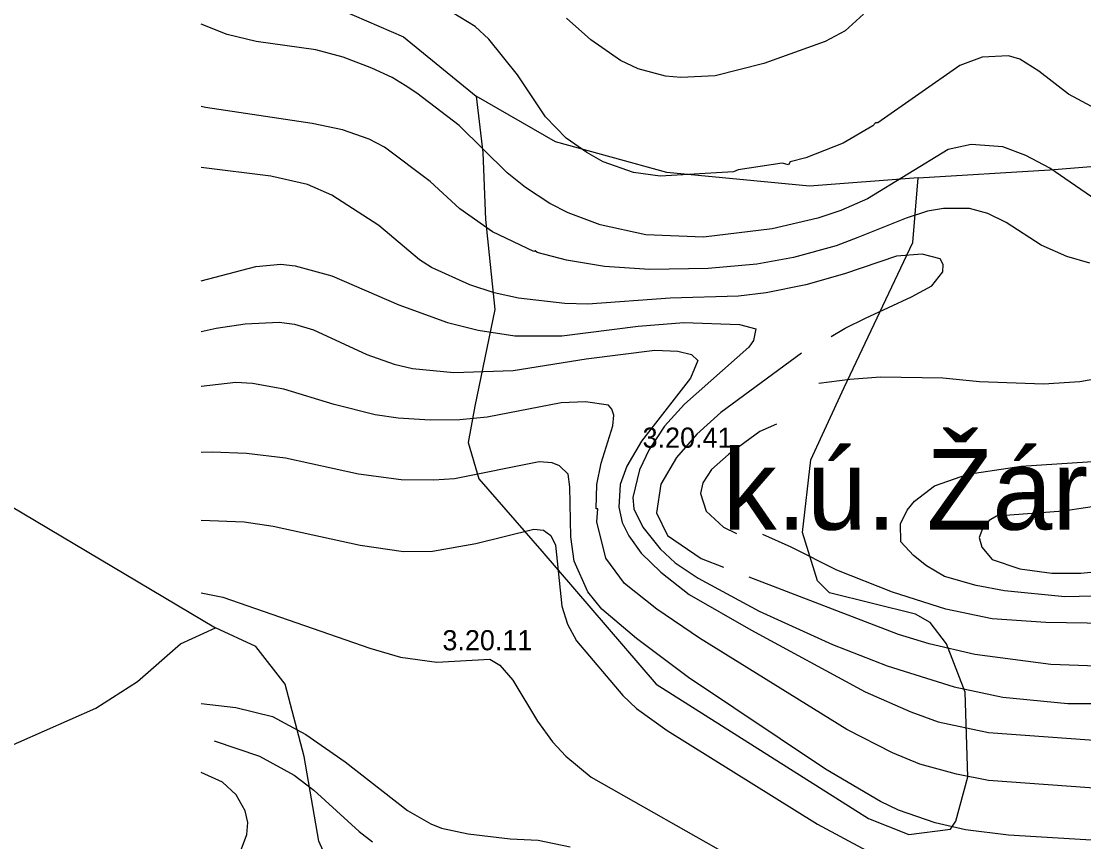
# Model space of a CAD drawing. Extents: x -662500 to -655523, y -1056000 to -1049993.
# Drawn here: x -661659.2 to -661263.9, y -1051925.7 to -1051620.1 of the extents above; entities that cross this region are included whole.
import ezdxf

# ---------------------------------------------------------------- set-up
doc = ezdxf.new("R2010")
doc.units = 0
for name, color, linetype in [('58', 7, 'Continuous'), ('Vrstva 24', 7, 'Continuous'), ('Vrstva 7', 7, 'Continuous')]:
    doc.layers.add(name, color=color, linetype=linetype)

msp = doc.modelspace()

# ---------------------------------------------------------------- linework, layer by layer
at = {"layer": 'Vrstva 24'}
for points in [[(-661544.5, -1051614), (-661517, -1051626), (-661490, -1051648)], [(-661490, -1051648), (-661487.5, -1051669), (-661486.5, -1051694), (-661483, -1051727.5), (-661490.5, -1051763.5), (-661493, -1051777), (-661489, -1051790.5), (-661465.5, -1051817.5), (-661423, -1051867), (-661344, -1051917), (-661329, -1051923), (-661313.5, -1051921), (-661311.5, -1051918), (-661307, -1051901.5), (-661308, -1051870), (-661315, -1051852), (-661321, -1051844), (-661326.5, -1051841), (-661358.5, -1051833), (-661363, -1051828.5), (-661368.5, -1051810.5), (-661365.5, -1051783.5), (-661353, -1051756.5), (-661327.5, -1051702.5), (-661325.5, -1051678.5)], [(-661325.5, -1051678.5), (-661366, -1051681.5), (-661419, -1051676.5), (-661460.5, -1051665), (-661490, -1051648)], [(-661325.5, -1051678.5), (-661276.5, -1051675.5), (-661191, -1051668.5), (-661149.5, -1051670), (-661133, -1051674), (-661124.5, -1051677.5), (-661112, -1051684), (-661104.5, -1051691.5), (-661026, -1051781.5), (-661005, -1051798), (-660983, -1051806.5), (-660947.48, -1051815.82)], [(-661882, -1051673), (-661865.5, -1051680), (-661808.5, -1051691), (-661771.5, -1051702.5), (-661762, -1051705), (-661744, -1051714.5), (-661731, -1051722), (-661713.5, -1051737.5), (-661704, -1051747), (-661687, -1051769), (-661663.5, -1051800.5), (-661587, -1051846)], [(-661750, -1052071.5), (-661753.5, -1052056), (-661750, -1052022), (-661748.36, -1052000), (-661747.5, -1051988.5), (-661737.5, -1051952.5), (-661720, -1051923.5), (-661698.5, -1051905.5), (-661631.5, -1051876), (-661616, -1051866), (-661600, -1051852), (-661587, -1051846)], [(-661191, -1052048), (-661295, -1052071.5), (-661327.5, -1052073.5), (-661352, -1052066.5), (-661463.18, -1052000), (-661512.5, -1051970.5), (-661540.5, -1051943.5), (-661548.5, -1051925.5), (-661554, -1051894), (-661561, -1051867), (-661572, -1051853), (-661587, -1051846)]]:
    msp.add_lwpolyline(points, dxfattribs=at)
at = {"layer": 'Vrstva 7'}
for p, q in [((-661490.38, -1051622.14), (-661501.71, -1051615.19)), ((-661345.83, -1051617.46), (-661352.63, -1051623.7)), ((-661582.62, -1051625.1), (-661592.25, -1051621.27)), ((-661447.29, -1051627.1), (-661456.36, -1051619.02)), ((-661571.86, -1051627.66), (-661582.62, -1051625.1)), ((-661485.27, -1051626.81), (-661490.38, -1051622.14)), ((-661352.63, -1051623.7), (-661360.14, -1051627.66)), ((-661549.61, -1051630.78), (-661571.86, -1051627.66)), ((-661474.65, -1051640.14), (-661485.27, -1051626.81)), ((-661436.24, -1051634.75), (-661447.29, -1051627.1)), ((-661360.14, -1051627.66), (-661382.95, -1051635.88)), ((-661539.41, -1051633.47), (-661549.61, -1051630.78)), ((-661291.97, -1051633.05), (-661301.75, -1051633.47)), ((-661287.72, -1051634.32), (-661291.97, -1051633.05)), ((-661528.78, -1051637.58), (-661539.41, -1051633.47)), ((-661429.72, -1051637.87), (-661436.24, -1051634.75)), ((-661382.95, -1051635.88), (-661401.09, -1051640.42)), ((-661309.97, -1051636.59), (-661340.58, -1051657.99)), ((-661301.75, -1051633.47), (-661309.97, -1051636.59)), ((-661280.64, -1051638.72), (-661287.72, -1051634.32)), ((-661521.23, -1051641.12), (-661528.78, -1051637.58)), ((-661516.43, -1051644.1), (-661521.23, -1051641.12)), ((-661464.16, -1051655.72), (-661474.65, -1051640.14)), ((-661419.52, -1051640.56), (-661429.72, -1051637.87)), ((-661413.85, -1051641.13), (-661419.52, -1051640.56)), ((-661401.09, -1051640.42), (-661413.85, -1051641.13)), ((-661269.58, -1051647.36), (-661280.64, -1051638.72)), ((-661512.06, -1051646.88), (-661516.43, -1051644.1)), ((-661496.3, -1051659.01), (-661512.06, -1051646.88)), ((-661261.08, -1051651.9), (-661269.58, -1051647.36)), ((-661590.71, -1051652.32), (-661592.25, -1051651.94)), ((-661551.03, -1051658.27), (-661590.71, -1051652.32)), ((-661456.51, -1051663.66), (-661464.16, -1051655.72)), ((-661539.69, -1051660.54), (-661551.03, -1051658.27)), ((-661529.77, -1051664.08), (-661539.69, -1051660.54)), ((-661478.47, -1051676.56), (-661496.3, -1051659.01)), ((-661342.42, -1051659.12), (-661353.48, -1051665.5)), ((-661341.43, -1051657.99), (-661342.42, -1051659.12)), ((-661340.58, -1051657.99), (-661341.43, -1051657.99)), ((-661524.1, -1051667.06), (-661529.77, -1051664.08)), ((-661448.85, -1051669.04), (-661456.51, -1051663.66)), ((-661507.1, -1051679.81), (-661524.1, -1051667.06)), ((-661442.76, -1051672.45), (-661448.85, -1051669.04)), ((-661353.48, -1051665.5), (-661367.37, -1051671.03)), ((-661314.36, -1051667.91), (-661344.41, -1051686.33)), ((-661305.86, -1051666.07), (-661314.36, -1051667.91)), ((-661293.96, -1051666.92), (-661305.86, -1051666.07)), ((-661285.45, -1051670.18), (-661293.96, -1051666.92)), ((-661431.42, -1051676.41), (-661442.76, -1051672.45)), ((-661373.18, -1051672.45), (-661373.74, -1051673.58)), ((-661367.37, -1051671.03), (-661373.18, -1051672.45)), ((-661276.53, -1051674.85), (-661285.45, -1051670.18)), ((-661566.34, -1051677.83), (-661592.25, -1051674.67)), ((-661471.67, -1051682.08), (-661478.47, -1051676.56)), ((-661421.5, -1051677.83), (-661431.42, -1051676.41)), ((-661394.29, -1051676.27), (-661421.5, -1051677.83)), ((-661392.45, -1051675.42), (-661394.29, -1051676.27)), ((-661376.15, -1051673.01), (-661392.45, -1051675.42)), ((-661373.74, -1051673.58), (-661376.15, -1051673.01)), ((-661257.4, -1051688.03), (-661276.53, -1051674.85)), ((-661552.73, -1051680.95), (-661566.34, -1051677.83)), ((-661496.05, -1051690.02), (-661507.1, -1051679.81)), ((-661543.66, -1051684.92), (-661552.73, -1051680.95)), ((-661462.6, -1051688.03), (-661471.67, -1051682.08)), ((-661526.23, -1051696.25), (-661543.66, -1051684.92)), ((-661455.8, -1051691.44), (-661462.6, -1051688.03)), ((-661344.41, -1051686.33), (-661354.33, -1051690.59)), ((-661483.86, -1051698.52), (-661496.05, -1051690.02)), ((-661443.89, -1051695.97), (-661455.8, -1051691.44)), ((-661354.33, -1051690.59), (-661362.83, -1051693.42)), ((-661322.02, -1051690.87), (-661329.95, -1051693.42)), ((-661316.07, -1051689.88), (-661322.02, -1051690.87)), ((-661306.43, -1051689.88), (-661316.07, -1051689.88)), ((-661299.63, -1051691.72), (-661306.43, -1051689.88)), ((-661292.82, -1051695.12), (-661299.63, -1051691.72)), ((-661511.07, -1051709.01), (-661526.23, -1051696.25)), ((-661426.89, -1051699.66), (-661443.89, -1051695.97)), ((-661362.83, -1051693.42), (-661379.84, -1051697.39)), ((-661329.95, -1051693.42), (-661346.11, -1051699.94)), ((-661279.79, -1051703.48), (-661292.82, -1051695.12)), ((-661468.55, -1051705.89), (-661483.86, -1051698.52)), ((-661405.35, -1051700.51), (-661426.89, -1051699.66)), ((-661379.84, -1051697.39), (-661405.35, -1051700.51)), ((-661347.95, -1051700.65), (-661356.03, -1051703.77)), ((-661346.11, -1051699.94), (-661347.95, -1051700.65)), ((-661356.03, -1051703.77), (-661371.9, -1051708.16)), ((-661270.15, -1051707.73), (-661279.79, -1051703.48)), ((-661467.98, -1051705.61), (-661468.55, -1051705.89)), ((-661467.28, -1051706.32), (-661467.98, -1051705.61)), ((-661456.36, -1051709.15), (-661467.28, -1051706.32)), ((-661371.9, -1051708.16), (-661385.51, -1051710.57)), ((-661333.64, -1051707.59), (-661352.91, -1051714.25)), ((-661324, -1051706.88), (-661333.64, -1051707.59)), ((-661317.34, -1051708.58), (-661324, -1051706.88)), ((-661261.65, -1051710.28), (-661270.15, -1051707.73)), ((-661592.25, -1051716.86), (-661572.01, -1051711.42)), ((-661592.25, -1051716.86), (-661572.01, -1051711.42)), ((-661572.01, -1051711.42), (-661562.65, -1051710.57)), ((-661572.01, -1051711.42), (-661562.65, -1051710.57)), ((-661562.65, -1051710.57), (-661557.27, -1051711.28)), ((-661562.65, -1051710.57), (-661557.27, -1051711.28)), ((-661557.27, -1051711.28), (-661543.66, -1051714.96)), ((-661557.27, -1051711.28), (-661543.66, -1051714.96)), ((-661506.53, -1051711.84), (-661511.07, -1051709.01)), ((-661492.36, -1051718.36), (-661506.53, -1051711.84)), ((-661442.19, -1051711.42), (-661456.36, -1051709.15)), ((-661425.47, -1051712.55), (-661442.19, -1051711.42)), ((-661403.65, -1051712.27), (-661425.47, -1051712.55)), ((-661385.51, -1051710.57), (-661403.65, -1051712.27)), ((-661316.21, -1051710.71), (-661317.34, -1051708.58)), ((-661316.35, -1051713.4), (-661316.21, -1051710.71)), ((-661543.66, -1051714.96), (-661518.72, -1051725.73)), ((-661543.66, -1051714.96), (-661518.72, -1051725.73)), ((-661352.91, -1051714.25), (-661367.37, -1051718.36)), ((-661320.46, -1051718.65), (-661316.35, -1051713.4)), ((-661483.29, -1051721.34), (-661492.36, -1051718.36)), ((-661367.37, -1051718.36), (-661382.1, -1051721.34)), ((-661327.97, -1051722.76), (-661320.46, -1051718.65)), ((-661474.22, -1051723.32), (-661483.29, -1051721.34)), ((-661456.93, -1051725.31), (-661474.22, -1051723.32)), ((-661417.82, -1051723.32), (-661448.43, -1051725.45)), ((-661392.31, -1051722.47), (-661417.82, -1051723.32)), ((-661382.1, -1051721.34), (-661392.31, -1051722.47)), ((-661345.09, -1051730.72), (-661327.97, -1051722.76)), ((-661518.72, -1051725.73), (-661500.58, -1051732.39)), ((-661518.72, -1051725.73), (-661500.58, -1051732.39)), ((-661448.43, -1051725.45), (-661456.93, -1051725.31)), ((-661575.97, -1051732.82), (-661563.22, -1051732.25)), ((-661575.97, -1051732.82), (-661563.22, -1051732.25)), ((-661563.22, -1051732.25), (-661557.55, -1051732.96)), ((-661563.22, -1051732.25), (-661557.55, -1051732.96)), ((-661352.65, -1051734.48), (-661345.09, -1051730.72)), ((-661592.25, -1051735.65), (-661586.74, -1051734.38)), ((-661592.25, -1051735.65), (-661586.74, -1051734.38)), ((-661586.74, -1051734.38), (-661575.97, -1051732.82)), ((-661586.74, -1051734.38), (-661575.97, -1051732.82)), ((-661557.55, -1051732.96), (-661550.46, -1051735.08)), ((-661557.55, -1051732.96), (-661550.46, -1051735.08)), ((-661550.46, -1051735.08), (-661530.62, -1051744.3)), ((-661550.46, -1051735.08), (-661530.62, -1051744.3)), ((-661500.58, -1051732.39), (-661489.24, -1051735.23)), ((-661500.58, -1051732.39), (-661489.24, -1051735.23)), ((-661489.24, -1051735.23), (-661475.64, -1051737.35)), ((-661489.24, -1051735.23), (-661475.64, -1051737.35)), ((-661458.07, -1051737.35), (-661429.72, -1051733.67)), ((-661458.07, -1051737.35), (-661429.72, -1051733.67)), ((-661429.72, -1051733.67), (-661412.72, -1051732.39)), ((-661429.72, -1051733.67), (-661412.72, -1051732.39)), ((-661412.72, -1051732.39), (-661392.03, -1051733.1)), ((-661412.72, -1051732.39), (-661392.03, -1051733.1)), ((-661392.03, -1051733.1), (-661385.93, -1051734.66)), ((-661392.03, -1051733.1), (-661385.93, -1051734.66)), ((-661385.93, -1051734.66), (-661386.78, -1051739.05)), ((-661385.93, -1051734.66), (-661386.78, -1051739.05)), ((-661357.93, -1051737.48), (-661352.65, -1051734.48)), ((-661475.64, -1051737.35), (-661458.07, -1051737.35)), ((-661475.64, -1051737.35), (-661458.07, -1051737.35)), ((-661386.78, -1051739.05), (-661388.48, -1051741.46)), ((-661386.78, -1051739.05), (-661388.48, -1051741.46)), ((-661448.99, -1051745.85), (-661423.49, -1051742.6)), ((-661448.99, -1051745.85), (-661423.49, -1051742.6)), ((-661423.49, -1051742.6), (-661414.98, -1051743.02)), ((-661423.49, -1051742.6), (-661414.98, -1051743.02)), ((-661414.98, -1051743.02), (-661409.88, -1051744.3)), ((-661414.98, -1051743.02), (-661409.88, -1051744.3)), ((-661388.48, -1051741.46), (-661412.43, -1051762.72)), ((-661388.48, -1051741.46), (-661412.43, -1051762.72)), ((-661368.97, -1051743.8), (-661398.97, -1051765.84)), ((-661530.62, -1051744.3), (-661520.42, -1051747.84)), ((-661530.62, -1051744.3), (-661520.42, -1051747.84)), ((-661520.42, -1051747.84), (-661513.62, -1051749.4)), ((-661520.42, -1051747.84), (-661513.62, -1051749.4)), ((-661476.2, -1051750.25), (-661448.99, -1051745.85)), ((-661476.2, -1051750.25), (-661448.99, -1051745.85)), ((-661407.47, -1051746.42), (-661410.17, -1051753.08)), ((-661407.47, -1051746.42), (-661410.17, -1051753.08)), ((-661409.88, -1051744.3), (-661407.47, -1051746.42)), ((-661409.88, -1051744.3), (-661407.47, -1051746.42)), ((-661513.62, -1051749.4), (-661498.31, -1051750.96)), ((-661513.62, -1051749.4), (-661498.31, -1051750.96)), ((-661498.31, -1051750.96), (-661476.2, -1051750.25)), ((-661498.31, -1051750.96), (-661476.2, -1051750.25)), ((-661265.33, -1051754.36), (-661251.73, -1051751.81)), ((-661579.37, -1051754.64), (-661592.25, -1051756.19)), ((-661573.14, -1051755.07), (-661579.37, -1051754.64)), ((-661561.52, -1051757.19), (-661573.14, -1051755.07)), ((-661410.17, -1051753.08), (-661428.45, -1051776.47)), ((-661410.17, -1051753.08), (-661428.45, -1051776.47)), ((-661362.52, -1051754.92), (-661350.93, -1051753.37)), ((-661350.93, -1051753.37), (-661339.59, -1051752.52)), ((-661339.59, -1051752.52), (-661316.35, -1051752.94)), ((-661316.35, -1051752.94), (-661302.74, -1051754.36)), ((-661302.74, -1051754.36), (-661278.94, -1051755.21)), ((-661278.94, -1051755.21), (-661265.33, -1051754.36)), ((-661542.81, -1051762.86), (-661561.52, -1051757.19)), ((-661527.51, -1051766.69), (-661542.81, -1051762.86)), ((-661458.35, -1051762.29), (-661485.84, -1051767.54)), ((-661449.28, -1051761.87), (-661458.35, -1051762.29)), ((-661440.78, -1051763.15), (-661449.28, -1051761.87)), ((-661439.5, -1051764.56), (-661440.78, -1051763.15)), ((-661412.43, -1051762.72), (-661419.94, -1051770.94)), ((-661412.43, -1051762.72), (-661419.94, -1051770.94)), ((-661519, -1051767.96), (-661527.51, -1051766.69)), ((-661485.84, -1051767.54), (-661496.05, -1051768.53)), ((-661438.79, -1051766.83), (-661439.5, -1051764.56)), ((-661439.08, -1051770.8), (-661438.79, -1051766.83)), ((-661398.97, -1051765.84), (-661407.9, -1051773.92)), ((-661507.1, -1051768.67), (-661519, -1051767.96)), ((-661496.05, -1051768.53), (-661507.1, -1051768.67)), ((-661443.47, -1051784.69), (-661439.08, -1051770.8)), ((-661419.94, -1051770.94), (-661425.61, -1051779.58)), ((-661419.94, -1051770.94), (-661425.61, -1051779.58)), ((-661378.28, -1051770.23), (-661384.37, -1051772.92)), ((-661407.9, -1051773.92), (-661415.41, -1051782.56)), ((-661384.37, -1051772.92), (-661396.14, -1051781.43)), ((-661428.45, -1051776.47), (-661433.97, -1051785.82)), ((-661428.45, -1051776.47), (-661433.97, -1051785.82)), ((-661425.61, -1051779.58), (-661429.16, -1051787.24)), ((-661425.61, -1051779.58), (-661429.16, -1051787.24)), ((-661588.16, -1051780.58), (-661592.25, -1051780.7)), ((-661575.41, -1051781.14), (-661588.16, -1051780.58)), ((-661560.95, -1051782.84), (-661575.41, -1051781.14)), ((-661533.74, -1051788.79), (-661560.95, -1051782.84)), ((-661415.41, -1051782.56), (-661421.22, -1051792.48)), ((-661396.14, -1051781.43), (-661402.37, -1051787.09)), ((-661287.16, -1051785.82), (-661243.79, -1051782.99)), ((-661466.57, -1051784.26), (-661498.03, -1051790.5)), ((-661461.75, -1051784.54), (-661466.57, -1051784.26)), ((-661458.92, -1051785.68), (-661461.75, -1051784.54)), ((-661455.8, -1051788.8), (-661458.92, -1051785.68)), ((-661445.03, -1051792.62), (-661443.47, -1051784.69)), ((-661433.97, -1051785.82), (-661436.38, -1051792.62)), ((-661433.97, -1051785.82), (-661436.38, -1051792.62)), ((-661429.16, -1051787.24), (-661431.71, -1051797.44)), ((-661429.16, -1051787.24), (-661431.71, -1051797.44)), ((-661402.37, -1051787.09), (-661405.63, -1051792.05)), ((-661306.99, -1051788.79), (-661287.16, -1051785.82)), ((-661517.87, -1051790.92), (-661533.74, -1051788.79)), ((-661505.68, -1051791.06), (-661517.87, -1051790.92)), ((-661498.03, -1051790.5), (-661505.68, -1051791.06)), ((-661455.09, -1051793.47), (-661455.8, -1051788.8)), ((-661319.47, -1051793.19), (-661306.99, -1051788.79)), ((-661454.81, -1051812.18), (-661455.09, -1051793.47)), ((-661445.31, -1051801.69), (-661445.03, -1051792.62)), ((-661436.38, -1051792.62), (-661436.95, -1051801.12)), ((-661436.38, -1051792.62), (-661436.95, -1051801.12)), ((-661421.22, -1051792.48), (-661422.92, -1051803.25)), ((-661405.63, -1051792.05), (-661406.48, -1051796.02)), ((-661326.83, -1051798.86), (-661319.47, -1051793.19)), ((-661431.71, -1051797.44), (-661431.28, -1051801.69)), ((-661431.71, -1051797.44), (-661431.28, -1051801.69)), ((-661406.48, -1051796.02), (-661404.35, -1051802.54)), ((-661329.67, -1051802.26), (-661326.83, -1051798.86)), ((-661244.07, -1051798.43), (-661271.57, -1051802.54)), ((-661444.74, -1051801.69), (-661445.31, -1051801.69)), ((-661445.03, -1051806.51), (-661444.74, -1051801.69)), ((-661436.95, -1051801.12), (-661435.67, -1051806.79)), ((-661436.95, -1051801.12), (-661435.67, -1051806.79)), ((-661431.28, -1051801.69), (-661428.02, -1051808.49)), ((-661431.28, -1051801.69), (-661428.02, -1051808.49)), ((-661422.92, -1051803.25), (-661418.81, -1051811.61)), ((-661404.35, -1051802.54), (-661397.91, -1051808.56)), ((-661332.08, -1051807.36), (-661329.67, -1051802.26)), ((-661271.57, -1051802.54), (-661296.4, -1051804.42)), ((-661592.25, -1051805.95), (-661576.26, -1051806.51)), ((-661576.26, -1051806.51), (-661565.49, -1051808.21)), ((-661441.77, -1051820.11), (-661445.03, -1051806.51)), ((-661435.67, -1051806.79), (-661433.12, -1051811.75)), ((-661435.67, -1051806.79), (-661433.12, -1051811.75)), ((-661331.94, -1051814.02), (-661332.08, -1051807.36)), ((-661299.14, -1051806.02), (-661301.41, -1051808.75)), ((-661296.4, -1051804.42), (-661299.14, -1051806.02)), ((-661565.49, -1051808.21), (-661533.18, -1051815.3)), ((-661490.09, -1051814.59), (-661468.55, -1051809.34)), ((-661468.55, -1051809.34), (-661464.87, -1051809.72)), ((-661464.87, -1051809.72), (-661462.18, -1051811.61)), ((-661428.02, -1051808.49), (-661421.5, -1051816.57)), ((-661428.02, -1051808.49), (-661421.5, -1051816.57)), ((-661397.91, -1051808.56), (-661393.16, -1051810.9)), ((-661372.75, -1051816.01), (-661383.33, -1051811.28)), ((-661301.41, -1051808.75), (-661302.78, -1051812.4)), ((-661533.18, -1051815.3), (-661517.02, -1051817.56)), ((-661506.25, -1051817.42), (-661490.09, -1051814.59)), ((-661462.18, -1051811.61), (-661460.47, -1051815.3)), ((-661460.47, -1051815.3), (-661458.07, -1051837.97)), ((-661453.53, -1051821.25), (-661454.81, -1051812.18)), ((-661433.12, -1051811.75), (-661428.59, -1051818.27)), ((-661433.12, -1051811.75), (-661428.59, -1051818.27)), ((-661418.81, -1051811.61), (-661406.2, -1051820.26)), ((-661327.26, -1051819.12), (-661331.94, -1051814.02)), ((-661302.78, -1051812.4), (-661301.87, -1051815.94)), ((-661517.02, -1051817.56), (-661506.25, -1051817.42)), ((-661428.59, -1051818.27), (-661421.22, -1051825.36)), ((-661428.59, -1051818.27), (-661421.22, -1051825.36)), ((-661421.5, -1051816.57), (-661415.97, -1051821.81)), ((-661421.5, -1051816.57), (-661415.97, -1051821.81)), ((-661355.75, -1051824.51), (-661372.75, -1051816.01)), ((-661322.44, -1051822.95), (-661327.26, -1051819.12)), ((-661301.87, -1051815.94), (-661297.93, -1051820.54)), ((-661448.43, -1051832.59), (-661453.53, -1051821.25)), ((-661434.82, -1051829.47), (-661441.77, -1051820.11)), ((-661415.97, -1051821.81), (-661407.33, -1051827.48)), ((-661415.97, -1051821.81), (-661407.33, -1051827.48)), ((-661406.2, -1051820.26), (-661397.96, -1051823.42)), ((-661315.78, -1051826.92), (-661322.44, -1051822.95)), ((-661297.93, -1051820.54), (-661287.72, -1051824.08)), ((-661421.22, -1051825.36), (-661410.73, -1051833.58)), ((-661421.22, -1051825.36), (-661410.73, -1051833.58)), ((-661332.79, -1051848.46), (-661388.36, -1051827.11)), ((-661335.06, -1051832.73), (-661355.75, -1051824.51)), ((-661303.88, -1051830.32), (-661315.78, -1051826.92)), ((-661287.72, -1051824.08), (-661275.82, -1051825.64)), ((-661275.82, -1051825.64), (-661265.05, -1051825.64)), ((-661265.05, -1051825.64), (-661248.13, -1051824.07)), ((-661422.78, -1051839.1), (-661434.82, -1051829.47)), ((-661407.33, -1051827.48), (-661384.66, -1051839.81)), ((-661407.33, -1051827.48), (-661384.66, -1051839.81)), ((-661293.39, -1051832.3), (-661303.88, -1051830.32)), ((-661592.25, -1051832.94), (-661584.19, -1051834.57)), ((-661584.19, -1051834.57), (-661529.49, -1051853.56)), ((-661443.19, -1051839.1), (-661448.43, -1051832.59)), ((-661410.73, -1051833.58), (-661387.77, -1051846.76)), ((-661410.73, -1051833.58), (-661387.77, -1051846.76)), ((-661315.21, -1051839.1), (-661335.06, -1051832.73)), ((-661271, -1051834.43), (-661293.39, -1051832.3)), ((-661248.61, -1051834), (-661271, -1051834.43)), ((-661458.07, -1051837.97), (-661455.94, -1051844.63)), ((-661430.29, -1051850.02), (-661443.19, -1051839.1)), ((-661406.91, -1051849.88), (-661422.78, -1051839.1)), ((-661384.66, -1051839.81), (-661357.45, -1051852.28)), ((-661384.66, -1051839.81), (-661357.45, -1051852.28)), ((-661297.93, -1051842.65), (-661315.21, -1051839.1)), ((-661278.08, -1051844.06), (-661297.93, -1051842.65)), ((-661455.94, -1051844.63), (-661452.68, -1051850.87)), ((-661387.77, -1051846.76), (-661345.26, -1051869.86)), ((-661387.77, -1051846.76), (-661345.26, -1051869.86)), ((-661250.31, -1051844.49), (-661278.08, -1051844.06)), ((-661452.68, -1051850.87), (-661435.39, -1051871.27)), ((-661411.02, -1051864.47), (-661430.29, -1051850.02)), ((-661352.06, -1051883.89), (-661406.91, -1051849.88)), ((-661321.45, -1051852), (-661332.79, -1051848.46)), ((-661529.49, -1051853.56), (-661518.15, -1051856.96)), ((-661357.45, -1051852.28), (-661337.04, -1051860.22)), ((-661357.45, -1051852.28), (-661337.04, -1051860.22)), ((-661304.45, -1051855.97), (-661321.45, -1051852)), ((-661518.15, -1051856.96), (-661504.55, -1051858.8)), ((-661504.55, -1051858.8), (-661484.85, -1051857.67)), ((-661484.85, -1051857.67), (-661481.17, -1051859.94)), ((-661276.1, -1051859.65), (-661304.45, -1051855.97)), ((-661481.17, -1051859.94), (-661476.35, -1051865.46)), ((-661337.04, -1051860.22), (-661312.1, -1051868.02)), ((-661337.04, -1051860.22), (-661312.1, -1051868.02)), ((-661259.09, -1051860.36), (-661276.1, -1051859.65)), ((-661476.35, -1051865.46), (-661467.14, -1051880.77)), ((-661360, -1051898.63), (-661411.02, -1051864.47)), ((-661345.26, -1051869.86), (-661328.25, -1051877.37)), ((-661345.26, -1051869.86), (-661328.25, -1051877.37)), ((-661312.1, -1051868.02), (-661293.96, -1051871.84)), ((-661312.1, -1051868.02), (-661293.96, -1051871.84)), ((-661592.25, -1051874.24), (-661579.37, -1051875.67)), ((-661435.39, -1051871.27), (-661430.29, -1051876.09)), ((-661293.96, -1051871.84), (-661269.87, -1051874.25)), ((-661293.96, -1051871.84), (-661269.87, -1051874.25)), ((-661269.87, -1051874.25), (-661245.49, -1051874.25)), ((-661269.87, -1051874.25), (-661245.49, -1051874.25)), ((-661579.37, -1051875.67), (-661565.77, -1051879.07)), ((-661430.29, -1051876.09), (-661418.95, -1051884.31)), ((-661328.25, -1051877.37), (-661318.05, -1051881.05)), ((-661328.25, -1051877.37), (-661318.05, -1051881.05)), ((-661565.77, -1051879.07), (-661553.3, -1051885.73)), ((-661467.14, -1051880.77), (-661461.61, -1051888.42)), ((-661318.05, -1051881.05), (-661299.34, -1051885.02)), ((-661318.05, -1051881.05), (-661299.34, -1051885.02)), ((-661553.3, -1051885.73), (-661538.7, -1051895.93)), ((-661418.95, -1051884.31), (-661362.97, -1051919.17)), ((-661335.06, -1051892.53), (-661352.06, -1051883.89)), ((-661299.34, -1051885.02), (-661238.12, -1051889.41)), ((-661299.34, -1051885.02), (-661238.12, -1051889.41)), ((-661587.45, -1051888.14), (-661570.59, -1051893.81)), ((-661461.61, -1051888.42), (-661456.65, -1051893.81)), ((-661570.59, -1051893.81), (-661557.69, -1051900.89)), ((-661456.65, -1051893.81), (-661447.15, -1051901.6)), ((-661324.85, -1051896.78), (-661335.06, -1051892.53)), ((-661538.7, -1051895.93), (-661515.46, -1051914.07)), ((-661311.25, -1051900.47), (-661324.85, -1051896.78)), ((-661584.33, -1051903.44), (-661592.25, -1051899.84)), ((-661557.69, -1051900.89), (-661550.32, -1051906.42)), ((-661447.15, -1051901.6), (-661392.53, -1051932.69)), ((-661339.59, -1051910.67), (-661360, -1051898.63)), ((-661299.34, -1051902.88), (-661311.25, -1051900.47)), ((-661579.23, -1051908.26), (-661584.33, -1051903.44)), ((-661248.04, -1051906.56), (-661299.34, -1051902.88)), ((-661575.97, -1051914.22), (-661579.23, -1051908.26)), ((-661550.32, -1051906.42), (-661533.46, -1051921.87)), ((-661515.46, -1051914.07), (-661506.82, -1051919.03)), ((-661332.79, -1051913.93), (-661339.59, -1051910.67)), ((-661319.18, -1051918.61), (-661332.79, -1051913.93)), ((-661574.98, -1051918.47), (-661575.97, -1051914.22)), ((-661575.26, -1051923), (-661574.98, -1051918.47)), ((-661533.46, -1051921.87), (-661528.5, -1051925.69)), ((-661506.82, -1051919.03), (-661502.85, -1051920.59)), ((-661502.85, -1051920.59), (-661492.93, -1051922.72)), ((-661362.97, -1051919.17), (-661344.69, -1051928.95)), ((-661307.85, -1051921.3), (-661319.18, -1051918.61)), ((-661291.97, -1051923.28), (-661307.85, -1051921.3)), ((-661580.37, -1051936.61), (-661575.26, -1051923)), ((-661492.93, -1051922.72), (-661477.34, -1051924.56)), ((-661477.34, -1051924.56), (-661466.85, -1051925.13)), ((-661466.85, -1051925.13), (-661454.95, -1051927.54)), ((-661252.29, -1051925.69), (-661291.97, -1051923.28))]:
    msp.add_line(p, q, dxfattribs=at)

# ---------------------------------------------------------------- texts
at = {"layer": '58'}
msp.add_text('k.ú. Žáravice', height=30, dxfattribs=at).set_placement((-661398.23, -1051809.48))
at = {"layer": 'Vrstva 24'}
for s, p in [('3.20.41', (-661428.05, -1051778.96)), ('3.20.11', (-661502.53, -1051854.39))]:
    msp.add_text(s, height=7.5, dxfattribs=at).set_placement(p)

doc.saveas('drawing.dxf')
